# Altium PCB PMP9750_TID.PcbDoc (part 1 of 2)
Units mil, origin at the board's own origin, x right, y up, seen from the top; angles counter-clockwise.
Board outline 3800 x 2050 mil, 2 copper layers (Top Layer, Bottom Layer), stack 62 mil thick; 72 components, 37 nets, 177 pads, 17 vias.
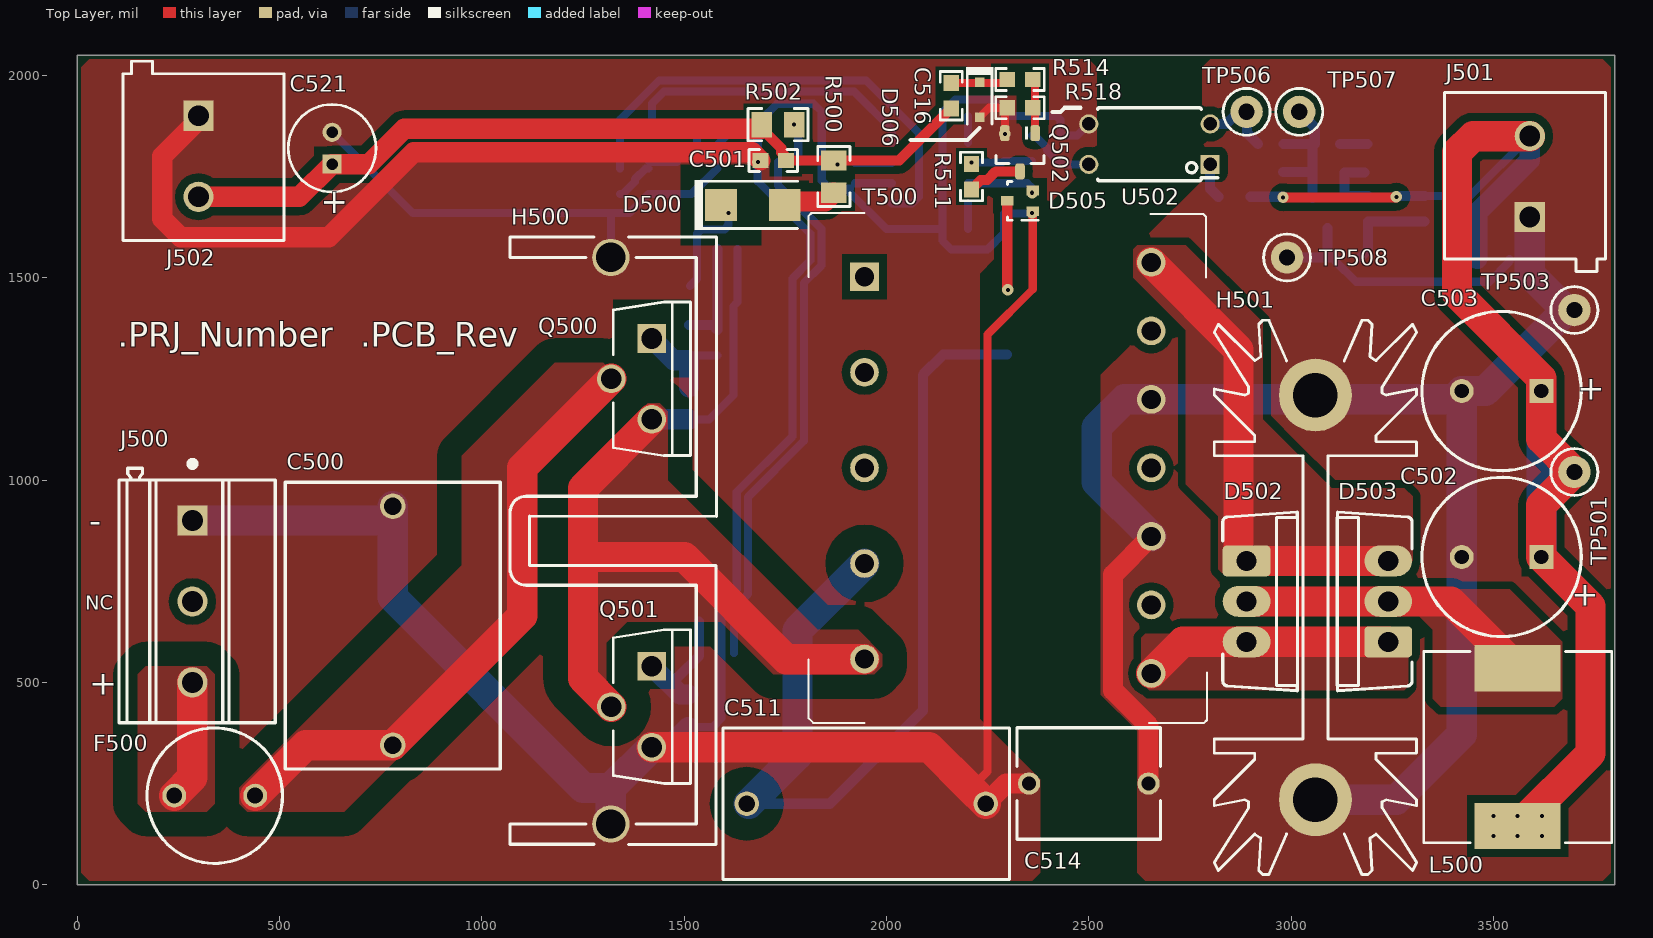
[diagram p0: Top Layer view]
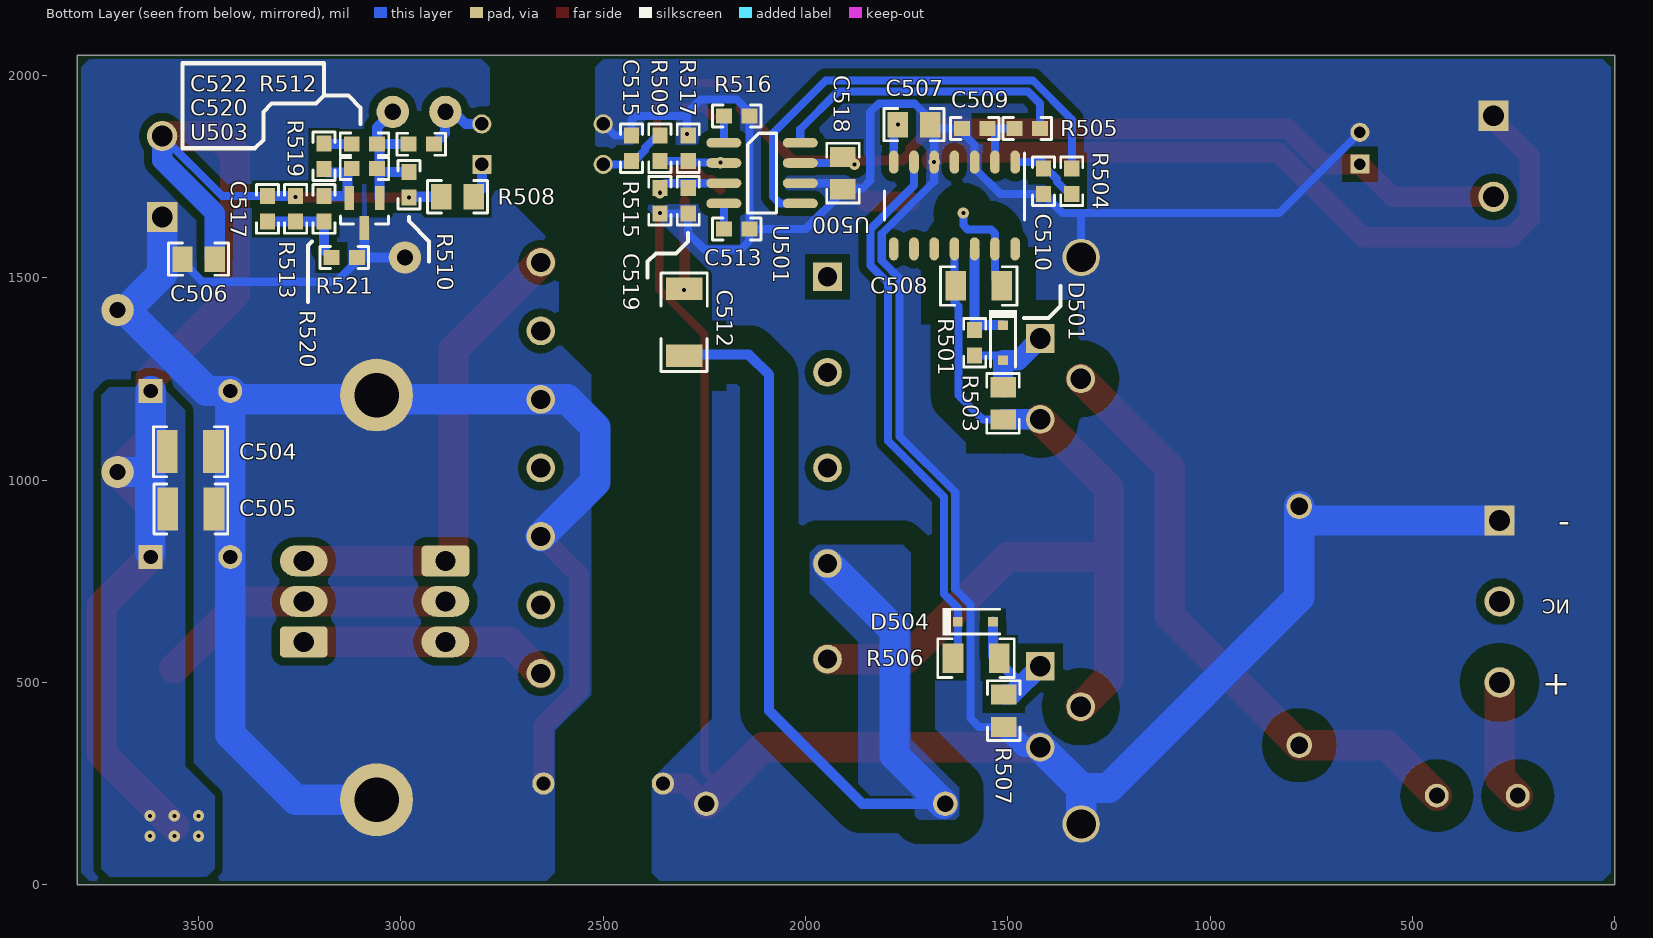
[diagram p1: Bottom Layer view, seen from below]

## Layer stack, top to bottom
Top Solder: solder mask 0.4, Solder Resist, Dk 3.5
Top Layer: signal copper 1.4
Dielectric1: core 59.2, FR-4, Dk 4.8
Bottom Layer: signal copper 1.4
Bottom Solder: solder mask 0.4, Solder Resist, Dk 3.5

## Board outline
0,0 3800,0 3800,2050 0,2050

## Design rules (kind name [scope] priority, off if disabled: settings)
AcuteAngle [All] p1: minimum=4.50000000000000E+0001 checktracksonly=FALSE
AssemblyTestPointUsage [All] p1: valid=2
Clearance Clearance_1 [InNetClass('HV_pri') vs InNet('GND')] p1: gap=60
Clearance Clearance_Keepouts [((IsTrack Or IsArc) And Not InPoly) And IsFree and IsKeepOut vs ((IsTrack Or IsArc) And Not InPoly) And IsFree and IsKeepOut] p2: gap=0
Clearance Clearance_BoardEdge_MountingHoles [OnCopper and InComponentClass('Mounting Holes') vs IsKeepOut] p3: gap=40
Clearance Clearance_BoardEdge_Poly [OnCopper and InPoly vs IsKeepOut] p4: gap=25
Clearance Clearance_BoardEdge [OnCopper and Not InComponentClass('Logo') and not InComponentClass('FiducialMark') and not InRegion(1000,500,4000,800) and Not IsKeepout vs IsKeepOut] p5: gap=75
Clearance Clearance_Poly [InPolygon] p6: gap=20
Clearance [All] p7: gap=7.87
ComponentClearance ComponentClearance_MountingHoles_FiducialMarks [InComponentClass('Mounting Holes') vs InComponentClass('FiducialMark')] p1: gap=20 collisioncheckmode=3 verticalgap=10 showdistances=FALSE
ComponentClearance ComponentClearance_Shunt [InComponentClass('Header') vs InComponentClass('Shunt')] p2: gap=0 collisioncheckmode=3 verticalgap=0 showdistances=FALSE
ComponentClearance ComponentClearance_Logo [InComponentClass('Logo')] p3: gap=5 collisioncheckmode=3 verticalgap=10 showdistances=FALSE
ComponentClearance ComponentClearance_ScrewToNut [(HasFootprint('NY PMS 440 0025 PH')) vs (HasFootprint('Keystone_1902C'))] p4: gap=20 collisioncheckmode=3 verticalgap=100000 showdistances=FALSE
ComponentClearance ComponentClearance_MountingHoles [InComponentClass('Mounting Holes')] p5: gap=20 collisioncheckmode=3 verticalgap=10 showdistances=FALSE
ComponentClearance ComponentClearance_SmallPassives [HasFootprint('0201*') or HasFootprint('0402*') or HasFootprint('0508') or HasFootprint('0603*') or HasFootprint('0612') or HasFootprint('0805*') or HasFootprint('0815*') or HasFootprint('0830*') or HasFootprint('1206*') or HasFootprint('1210*') or HasFootprint('1808*') or HasFootprint('1812*') or HasFootprint('1825*') or HasFootprint('2010*') or HasFootprint('2220*') or HasFootprint('2225*') or HasFootprint('2512*') or HasFootprint('2728*') or HasFootprint('3518*') vs HasFootprint('0201*') or HasFootprint('0402*') or HasFootprint('0508') or HasFootprint('0603*') or HasFootprint('0612') or HasFootprint('0805*') or HasFootprint('0815*') or HasFootprint('0830*') or HasFootprint('1206*') or HasFootprint('1210*') or HasFootprint('1808*') or HasFootprint('1812*') or HasFootprint('1825*') or HasFootprint('2010*') or HasFootprint('2220*') or HasFootprint('2225*') or HasFootprint('2512*') or HasFootprint('2728*') or HasFootprint('3518*')] p6: gap=20 collisioncheckmode=3 verticalgap=20 showdistances=FALSE
ComponentClearance ComponentClearance_THtoSMT [IsThruComponent vs IsSMTComponent] p7: gap=10 collisioncheckmode=3 verticalgap=10 showdistances=FALSE
ComponentClearance ComponentClearance_THtoTH [IsThruComponent vs IsThruComponent] p8: gap=10 collisioncheckmode=3 verticalgap=10 showdistances=FALSE
ComponentClearance [All] p9: gap=10 collisioncheckmode=3 verticalgap=10 showdistances=FALSE
DiffPairsRouting [All] p1: maxlimit=100 minlimit=10 mostfreqgap=10 toplayer_minwidth=15 toplayer_maxwidth=15 toplayer_prefwidth=15 bottomlayer_minwidth=15 bottomlayer_maxwidth=15 bottomlayer_prefwidth=15 maxuncoupledlength=1000
FabricationTestPointUsage TestPointUsage [All] p1: valid=2 allowmultiple=FALSE
FabricationTestpoint Testpoint [All] p1: side=3 testpointundercomponent=TRUE minsize=40 maxsize=100 preferedsize=60 minholesize=0 maxholesize=40 preferedholesize=32 testpointgrid=1 allowsidetop=TRUE allowsidebottom=TRUE usegrid=TRUE gridtolerance=0.01
FanoutControl Fanout_LCC [IsLCC] p1: bgadir=Out bgaviamode=Centered fanoutstyle=Auto fanoutdirection=Alternating viagrid=1 // Fanout_LCC (Default Rule)
FanoutControl Fanout_BGA [IsBGA] p2: bgadir=Out bgaviamode=Centered fanoutstyle=Auto fanoutdirection=Alternating viagrid=1 // Fanout_BGA (Default Rule)
FanoutControl Fanout_Default [All] p4: bgadir=Out bgaviamode=Centered fanoutstyle=Auto fanoutdirection=Alternating viagrid=1 // Fanout_Default (Default Rule)
FanoutControl Fanout_Small [(CompPinCount < 5)] p5: bgadir=Out bgaviamode=Centered fanoutstyle=Auto fanoutdirection=OutThenIn viagrid=1 // Fanout_Small (Default Rule)
Height [All] p1: minheight=0 maxheight=3000 prefheight=500
HoleSize [All] p1: absolutevalues=TRUE maxlimit=251 minlimit=7 maxpercent=80.000 minpercent=20.000
MinimumAnnularRing MinimumAnnularRing_ThermalPadVias [IsVia and InAnyComponent] p1: minimumring=5.91
MinimumAnnularRing [All] p2: minimumring=6
MinimumSolderMaskSliver MinimumSolderMaskSliver_Logo [InComponentClass('Logo') vs InComponentClass('Logo')] p1: minsoldermaskwidth=0.7
MinimumSolderMaskSliver [All] p2: minsoldermaskwidth=2
PlaneConnect [All] p1: planeconnectstyle=Relief reliefexpansion=10 reliefentries=4 reliefconductorwidth=10 reliefairgap=10
PolygonConnect PolygonConnect_8 [All vs IsNamedPolygon('C508_2') Or  IsNamedPolygon('B+') Or  IsNamedPolygon('Vout') Or  IsNamedPolygon('VSEC') Or  IsNamedPolygon('D502_3') Or  IsNamedPolygon('F500_2') Or  IsNamedPolygon('VCS') Or  IsNamedPolygon('D502_1')] p1: connectstyle=Direct reliefconductorwidth=10 reliefentries=4 polygonreliefangle="90 Angle" airgapwidth=10
PolygonConnect PolygonConnect_7 [All vs IsNamedPolygon('C508_2') Or  IsNamedPolygon('D502_1') Or  IsNamedPolygon('VCS') Or  IsNamedPolygon('D502_3') Or  IsNamedPolygon('B+')] p2: connectstyle=Direct reliefconductorwidth=10 reliefentries=4 polygonreliefangle="90 Angle" airgapwidth=10
PolygonConnect PolygonConnect_6 [All vs IsNamedPolygon('GND2') Or  IsNamedPolygon('SGND') Or  IsNamedPolygon('GND1') Or  IsNamedPolygon('C901_1') Or  IsNamedPolygon('SGND') Or  IsNamedPolygon('GND2') Or  IsNamedPolygon('GND1')] p3: connectstyle=Direct reliefconductorwidth=10 reliefentries=4 polygonreliefangle="90 Angle" airgapwidth=10
PolygonConnect PolygonConnect_5 [All vs IsNamedPolygon('GND1') Or  IsNamedPolygon('GND1')] p4: connectstyle=Direct reliefconductorwidth=10 reliefentries=4 polygonreliefangle="90 Angle" airgapwidth=10
PolygonConnect PolygonConnect_4 [All vs IsNamedPolygon('C21_1') Or  IsNamedPolygon('C5_1') Or  IsNamedPolygon('C12_2') Or  IsNamedPolygon('C2_2') Or  IsNamedPolygon('C13_1') Or  IsNamedPolygon('C28_1') Or  IsNamedPolygon('C6_1') Or  IsNamedPolygon('GND') Or  IsNamedPolygon('GND2') Or  IsNamedPolygon('C14_1') Or  IsNamedPolygon('C13_1') Or  IsNamedPolygon('Q1_3') Or  IsNamedPolygon('C14_1') Or  IsNamedPolygon('C5_1') Or  IsNamedPolygon('GND2') Or  IsNamedPolygon('C28_1') Or  IsNamedPolygon('D5_2') Or  IsNamedPolygon('D6_2') Or  IsNamedPolygon('D2_1') Or  IsNamedPolygon('C12_2') Or  IsNamedPolygon('D2_1') Or  IsNamedPolygon('C4_1') Or  IsNamedPolygon('C4_1') Or  IsNamedPolygon('C2_2') Or  IsNamedPolygon('GND') Or  IsNamedPolygon('C33_1') Or  IsNamedPolygon('C9_1')] p5: connectstyle=Direct reliefconductorwidth=10 reliefentries=4 polygonreliefangle="90 Angle" airgapwidth=10
PolygonConnect PolygonConnect_3 [All vs IsNamedPolygon('C28_1') Or  IsNamedPolygon('C12_2') Or  IsNamedPolygon('C28_1') Or  IsNamedPolygon('C9_1') Or  IsNamedPolygon('D5_2') Or  IsNamedPolygon('C12_2') Or  IsNamedPolygon('C2_2') Or  IsNamedPolygon('C14_1') Or  IsNamedPolygon('C4_1') Or  IsNamedPolygon('C14_1') Or  IsNamedPolygon('D6_2') Or  IsNamedPolygon('GND2') Or  IsNamedPolygon('Q1_3') Or  IsNamedPolygon('C5_1') Or  IsNamedPolygon('D2_1') Or  IsNamedPolygon('C4_1') Or  IsNamedPolygon('C13_1') Or  IsNamedPolygon('C5_1') Or  IsNamedPolygon('C13_1') Or  IsNamedPolygon('C33_1') Or  IsNamedPolygon('D2_1') Or  IsNamedPolygon('GND') Or  IsNamedPolygon('GND') Or  IsNamedPolygon('GND2') Or  IsNamedPolygon('C2_2') Or  IsNamedPolygon('C6_1') Or  IsNamedPolygon('C21_1')] p6: connectstyle=Direct reliefconductorwidth=10 reliefentries=4 polygonreliefangle="90 Angle" airgapwidth=10
PolygonConnect PolygonConnect_2 [All vs IsNamedPolygon('C21_1') Or  IsNamedPolygon('C4_1') Or  IsNamedPolygon('D5_2') Or  IsNamedPolygon('C5_1') Or  IsNamedPolygon('C14_1') Or  IsNamedPolygon('C13_1') Or  IsNamedPolygon('C4_1') Or  IsNamedPolygon('C33_1') Or  IsNamedPolygon('C12_2') Or  IsNamedPolygon('D2_1') Or  IsNamedPolygon('C2_2') Or  IsNamedPolygon('C28_1') Or  IsNamedPolygon('C12_2') Or  IsNamedPolygon('D2_1') Or  IsNamedPolygon('C5_1') Or  IsNamedPolygon('Q1_3') Or  IsNamedPolygon('GND') Or  IsNamedPolygon('D6_2') Or  IsNamedPolygon('C6_1') Or  IsNamedPolygon('C2_2') Or  IsNamedPolygon('C14_1') Or  IsNamedPolygon('C28_1') Or  IsNamedPolygon('C13_1') Or  IsNamedPolygon('C9_1') Or  IsNamedPolygon('GND')] p7: connectstyle=Direct reliefconductorwidth=10 reliefentries=4 polygonreliefangle="90 Angle" airgapwidth=10
PolygonConnect PolygonConnect_1 [All vs IsNamedPolygon('C28_1') Or  IsNamedPolygon('D5_2') Or  IsNamedPolygon('C5_1') Or  IsNamedPolygon('C5_1') Or  IsNamedPolygon('D2_1') Or  IsNamedPolygon('C21_1') Or  IsNamedPolygon('C9_1') Or  IsNamedPolygon('C4_1') Or  IsNamedPolygon('C14_1') Or  IsNamedPolygon('C28_1') Or  IsNamedPolygon('C6_1') Or  IsNamedPolygon('C12_2') Or  IsNamedPolygon('C33_1') Or  IsNamedPolygon('C4_1') Or  IsNamedPolygon('C13_1') Or  IsNamedPolygon('C12_2') Or  IsNamedPolygon('D6_2') Or  IsNamedPolygon('C2_2') Or  IsNamedPolygon('C14_1') Or  IsNamedPolygon('D2_1') Or  IsNamedPolygon('C2_2') Or  IsNamedPolygon('C13_1')] p8: connectstyle=Direct reliefconductorwidth=10 reliefentries=4 polygonreliefangle="90 Angle" airgapwidth=10
PolygonConnect [All] p9: connectstyle=Relief reliefconductorwidth=10 reliefentries=4 polygonreliefangle="90 Angle" airgapwidth=10
RoutingVias ThermalPadVias [IsVia and InAnyComponent] p1: holewidth=7.87 width=19.68 viastyle="Through Hole" minholewidth=7.87 minwidth=19.68 maxholewidth=12.99 maxwidth=23.62
RoutingVias [All] p2: holewidth=16 width=34 viastyle="Through Hole" minholewidth=7.87 minwidth=26 maxholewidth=40 maxwidth=65
SilkToBoardRegionClearance [Not ((IsComment or IsDesignator) And (Hide <> 'False')) and not InRegion(1000,500,4000,800)] p1:
SilkToSilkClearance SilkToSilkClearance_Pb-FreeLogo [(HasFootprint('Pb-Free_Overlay_Medium') OR HasFootprint('Pb-Free_Overlay_Small')) vs (HasFootprint('Pb-Free_Overlay_Medium') OR HasFootprint('Pb-Free_Overlay_Small'))] p1: silktosilkclearance=0
SilkToSilkClearance [All] p2: silktosilkclearance=1
SilkToSolderMaskClearance "Silk to Solder Mask Opening" [All] p1: minsilkscreentomaskgap=1 clearancetoexposedcopper=FALSE
SolderMaskExpansion [All] p1: expansion=1.97
UnpouredPolygon [All] p1: allowunpoured=FALSE
Width [All] p1: maxlimit=100 minlimit=6 preferedwidth=10 checkconnectedcopper=TRUE
13 further rules are at their usual default settings.

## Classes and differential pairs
net class HV_pri: B+ NetC508_1 NetC508_2 NetD501_2 NetF500_2 VCS
net class Sec: GND2 NetC517_2 NetC520_1 NetC520_2 NetC522_1 NetD502_1 NetD502_3 NetR508_1 NetR512_1 VOUT VSEC
net class LV_pri: BIAS GND NetC507_2 NetC509_1 NetC510_1 NetC512_2 NetC513_1 NetC515_1 NetC516_2 NetC519_1 NetD500_2 NetD504_1 NetD504_2 NetQ502_1 NetQ502_3 NetR504_1 NetR505_1 NetR509_1 NetR516_2

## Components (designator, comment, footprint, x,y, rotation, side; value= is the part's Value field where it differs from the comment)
C500 "450MPK225J" MPK_1800x2000x1350 780,640 r90 top
C501 "UMK107AB7105KA-T" 0603 1720,1790 r0 top
C502 "35ZLH1000MEFC12.5X20" CAPPR5-10X20 3520,810 r180 top
C503 "35ZLH1000MEFC12.5X20" CAPPR5-10X20 3520,1220 r180 top
C504 "C3225X7R1H335M" 1210 3520,1070 r180 bottom
C505 "C3225X7R1H335M" 1210 3519,928.5 r180 bottom
C506 "08055C104KAT2A" 0805_HV 3500,1546 r0 bottom
C507 "GMK212B7105KG-T" 0805_HV 1732,1878.5 r0 bottom
C508 "12065C104KAT2A" 1206 1572,1479.6 r0 bottom
C509 "C0603C220J5GACTU" 0603 1582,1868.5 r0 bottom
C510 "C0603C220J5GACTU" 0603 1412,1738.5 r270 bottom
C511 "121MPE333J" CAPRR1500W80L1800T950H1800 1950,200 r0 top
C512 "VJ1808Y101KXEAT5Z" 1808 2300,1390 r90 bottom
C513 "C0603C474K4RACTU" 0603 2170,1620 r180 bottom
C514 "DE6E3KJ222MN3A" E_900x700x900 2500,250 r180 top
C515 "C0603C103K5RACTU" 0603 2430,1820 r90 bottom
C516 "06033C104JAT2A" 0603 2160,1950 r90 top
C517 "C0603C222K5RAC" 0603 3330,1670 r270 bottom
C518 "08053C224JAT2A" 0805_HV 1907.43,1758.5 r270 bottom
C519 "C0603C105K4PACTU" 0603 2290,1690 r270 bottom
C520 "C1608C0G1H101J" 0603 3090,1770 r180 bottom
C521 "25ML22MEFC5X5" ML_500x500 630,1820 r90 top
C522 "06031C332KAT2A" 0603 3090,1830 r180 bottom
D500 "BYG20J-E3/TR" SMA 1670,1680 r0 top
D501 "BAT54HT1G" sod-323 1512,1339.61 r270 bottom
D502 "VF40100C-E3/4W" TO-220AB 2890,700 r270 top
D503 "VF40100C-E3/4W" TO-220AB 3240,700 r90 top
D504 "BAT54HT1G" sod-323 1580,650 r180 bottom
D505 "BAV99WT1G" SOT-323 2330,1690 r180 top
D506 "MMDL914-TP" sod-323 2230,1940 r270 top
F500 "37212000001" FUSE_372 340,220 r180 top
H500 "578622B03200G" HSINK_578622B03200G 1320,850 r270 top
H501 "513002B02500G" HSINK_513201B02500 3060,710 r90 top
J500 "1715734" Phoenix_1715734 284.83,700 r270 top
J501 "1715721" PhoenixContact_1715721 3590,1750 r90 top
J502 "1715721" PhoenixContact_1715721 300,1800 r270 top
L500 "7443320100" WE-HCC_1210 3560,340 r270 top
Q500 "STP14NM50N" TO-220AB_100mil 1420,1350 r270 top
Q501 "STP14NM50N" TO-220AB_100mil 1420,540 r270 top
Q502 "FMMT620TA" SOT-23 2330,1810 r270 top
R500 "CRCW08052R20JNEA" 0805_HV 1870,1750 r270 top
R501 "CRCW06033R00JNEA" 0603 1582,1339.61 r270 bottom
R502 "ERJ-6RQF1R0V" 0805_HV 1732,1878.5 r180 top
R503 "CRCW080520K0FKEA" 0805_HV 1512,1189.6 r270 bottom
R504 "CRCW060351R1FKEA" 0603 1342,1738.5 r270 bottom
R505 "CRCW060351R1FKEA" 0603 1452,1868.5 r0 bottom
R506 "CRCW12063R30JNEA" 1206 1578.66,560 r180 bottom
R507 "CRCW080520K0FKEA" 0805_HV 1510,430 r270 bottom
R508 "CRCW08054K99FKEA" 0805_HV 2860,1700 r0 bottom
R509 "CRCW0603511RFKEA" 0603 2360,1820 r90 bottom
R510 "CRCW060310K0FKEA" 0603 2980,1730 r270 bottom
R511 "CRCW0603100RFKEA" 0603 2210,1750 r90 top
R512 "CRCW060315R0JNEA" 0603 2950,1830 r0 bottom
R513 "CRCW060325K5FKEA" 0603 3260,1670 r90 bottom
R514 "CRCW060349K9FKEA" 0603 2330,1990 r0 top
R515 "CRCW0603200RFKEA" 0603 2360,1690 r90 bottom
R516 "CRCW060320K0FKEA" 0603 2170,1900 r0 bottom
R517 "CRCW06033K40FKEA" 0603 2290,1820 r270 bottom
R518 "CRCW0603100KFKEA" 0603 2330,1920 r180 top
R519 "CRCW060310K0FKEA" 0603 3190,1800 r270 bottom
R520 "CRCW06031K00FKEA" 0603 3190,1670 r270 bottom
R521 "CRCW06032K49FKEA" 0603 3140,1550 r0 bottom
T500 "G135043LF" XFMR_GCI-1240x965x1213 2300,1030 r0 top
TP501 "5000" Keystone5000 3700,1020 r0 top
TP503 "5001" Keystone5001 3700,1420 r90 top
TP506 "5003" Keystone5003 2890,1910 r90 top
TP507 "5002" Keystone5002 3020,1910 r90 top
TP508 "5001" Keystone5001 2990,1550 r90 top
U500 "UCC27714D" D0014A_N 1632,1678.5 r270 bottom
U501 "UCC25600D" D0008A_N 2107.43,1758.5 r180 bottom
U502 "PC817X4NSZ0F" DIP762W60P254L460H350Q4B 2650,1830 r180 top
U503 "TL431ACDBZR" DBZ0003A_N 3090,1660 r270 bottom

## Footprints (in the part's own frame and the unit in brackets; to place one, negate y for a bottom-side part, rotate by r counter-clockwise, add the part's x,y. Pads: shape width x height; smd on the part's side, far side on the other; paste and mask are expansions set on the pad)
0603 [mm] "0603 from SM-752 data"
  rect 1x0.95 smd: 1(-0.8,0) 2(0.8,0)
  silkscreen extent -1.52,-0.69 1.52,0.69, body extent -0.87,-0.47 0.87,0.47, height 0.85
0805_HV [mil] "0805 with 30mil clearance between pads"
  rect 50x63 smd: 1(-40,0) 2(40,0)
  silkscreen extent -74,-40 74,40, body extent -43,-29 43,29, height 43
1206 [mm] "1206 from SM-752 data"
  rect 1.3x1.85 smd: 1(-1.45,0) 2(1.45,0)
  silkscreen extent -2.4,-1.21 2.4,1.21, body extent -1.7,-0.9 1.7,0.9, height 1.35
1210 [mm] "1210 from SM-752 data"
  rect 1.3x2.7 smd: 1(-1.45,0) 2(1.45,0)
  silkscreen extent -2.32,-1.57 2.32,1.57, body extent -1.7,-1.35 1.7,1.35, height 1.35
1808 [mm] "Chip Capacitor, Body 4.6x2.0mm, IPC Medium Density"
  rect 1.4x2.3 smd: 1(-2.1,0) 2(2.1,0)
  silkscreen extent -3.1,-1.45 3.1,1.45, body extent -2.47,-1.2 2.47,1.2, height 2.03
CAPPR5-10X20 [mm] "Capacitor, Electrolytic, Radial; Body 10 x 20 mm (Dia.xH typ); Pin Spacing 5 mm (typ)"
  rect 1.5x1.5 hole 0.9: 1(-2.5,0)
  round 1.5 hole 0.9: 2(2.5,0)
  silkscreen extent -5,-5 5,5, body extent -5.01,-5.01 5.01,5.01, height 22
CAPRR1500W80L1800T950H1800 [mm] "RUBYCON"
  round 1.55 hole 1.05: 1(-7.5,0) 2(7.5,0)
  silkscreen extent -9,-4.75 9,4.75, body extent -9,-4.75 9,4.75, height 19
D0008A_N [mm] "SOIC, 8-Leads, Body 4.9x3.9mm, Pitch 1.27mm, IPC Medium Density"
  oval 2.2x0.6 smd: 1(-2.4,1.905) 2(-2.4,0.635) 3(-2.4,-0.635) 4(-2.4,-1.905) 5(2.4,-1.905) 6(2.4,-0.635) 7(2.4,0.635) 8(2.4,1.905)
  silkscreen extent -0.9,-2.5 0.9,2.5, body extent -3,-2.45 3,2.45, height 1.63
D0014A_N [mm] "SOIC, 14-Leads, Body 8.7x3.9mm, Pitch 1.27mm, IPC Medium Density"
  oval 1.45x0.6 smd: 1(-2.725,3.81) 2(-2.725,2.54) 3(-2.725,1.27) 4(-2.725,0) 5(-2.725,-1.27) 6(-2.725,-2.54) 7(-2.725,-3.81) 8(2.725,-3.81) 9(2.725,-2.54) 10(2.725,-1.27) 11(2.725,0) 12(2.725,1.27) 13(2.725,2.54) 14(2.725,3.81)
  silkscreen extent -3.3,-4.4 0.9,4.4, body extent -3.02,-4.32 3.02,4.32, height 1.6
DBZ0003A_N [mm] "SOT23, 3-Leads, Body 2.9x1.3mm, Pitch 0.95mm, Lead Span 2.4mm, IPC Medium Density"
  rect 1.5x0.6 smd: 1(-0.95,0.95) 2(-0.95,-0.95) 3(0.95,0)
  silkscreen extent 0.2,-1.5 0.7,1.5, body extent -1.26,-1.46 1.26,1.46, height 0.96
DIP762W60P254L460H350Q4B [mm] "LITE-ON"
  rrect8% 1.2x1.2 hole 0.85: 1(-3.81,1.27)
  round 1.2 hole 0.85: 2(-3.81,-1.27) 3(3.81,-1.27) 4(3.81,1.27)
  silkscreen extent -4.29,-2.29 3.25,2.3, body extent -3.94,-2.29 3.94,2.3, height 4.3
E_900x700x900 [mm] "TH, 2- Leads, Body 9x7mm, Pin Spacing 7.5mm"
  round 1.4 hole 0.9: 1(-3.75,0) 2(3.75,0)
  silkscreen extent -4.5,-3.5 4.5,3.5, body extent -4.49,-3.5 4.49,3.5, height 11.96
FUSE_372 [mm] "LITTELFUSE"
  round 1.5 hole 1: 1(-2.54,0) 2(2.54,0)
  silkscreen extent -4.25,-4.25 4.25,4.25, body extent -4.26,-4.26 4.26,4.26, height 8
HSINK_513201B02500 [mil] "Aavid"
  round 180 hole 110.24: 1(-500,0) 2(500,0)
  silkscreen extent -685,-250 685,250, body extent -685,-250 685,250, height 2000
HSINK_578622B03200G [mm] "Twin Channel Style Heat Sink, TO-220"
  round 2.35 hole 1.85: 1(-17.78,-0.025) 2(17.78,-0.025)
  silkscreen extent -19.06,-6.35 19.07,6.6, body extent -19.06,-6.36 19.03,6.69, height 25.4
Keystone5000 [mil] "For Keystone 500x miniature loop terminals"
  round 80 hole 40: 1(0,0)
  silkscreen extent -58,-58 58,58, body extent -49,-49 49,49, height 182
Keystone5001 [mil] "For Keystone 500x miniature loop terminals"
  round 80 hole 40: 1(0,0)
  silkscreen extent -58,-58 58,58, body extent -49,-49 49,49, height 182
Keystone5002 [mil] "For Keystone 500x miniature loop terminals"
  round 80 hole 40: 1(0,0)
  silkscreen extent -58,-58 58,58, body extent -49,-49 49,49, height 182
Keystone5003 [mil] "For Keystone 500x miniature loop terminals"
  round 80 hole 40: 1(0,0)
  silkscreen extent -58,-58 58,58, body extent -49,-49 49,49, height 182
ML_500x500 [mm] "Rubycon"
  rect 1.2x1.2 hole 0.711: 1(-1,0)
  round 1.2 hole 0.711: 2(1,0)
  silkscreen extent -2.75,-2.75 2.75,2.75, body extent -2.73,-2.75 2.75,2.75, height 6.51
MPK_1800x2000x1350 [mm] "Rubycon"
  round 1.6 hole 1.1: 1(-7.5,0) 2(7.5,0)
  silkscreen extent -9,-6.75 9,6.75, body extent -9,-6.75 9,6.75, height 20
Phoenix_1715734 [mm] "Phoenix"
  rect 1.9x1.9 hole 1.321: 1(-5.08,0)
  round 1.9 hole 1.321: 2(0,0) 3(5.08,0)
  silkscreen extent -8.76,-4.6 7.62,5.2, body extent -8.36,-4.6 7.62,5.2, height 14.2
PhoenixContact_1715721 [mm] "Phoenix Contact 1715721 used on LM3445 design from Longmont"
  rect 1.905x1.905 hole 1.3: 1(-2.54,0)
  round 1.9 hole 1.3: 2(2.54,0)
  silkscreen extent -5.97,-4.75 5.28,5.36, body extent -5.82,-4.6 5.08,5.2, height 14.2
SMA [mm] "Molded Diode, 2-Leads, Body 4.3x2.6mm, IPC Medium Density, based on OnSemi component dimensions and land pattern"
  rect 2x2 smd: 1(-2,0) 2(2,0)
  silkscreen extent -3.66,-1.57 2.79,1.57, body extent -2.6,-1.3 2.6,1.3, height 2.42
sod-323 [mm] "NXP recommended land pattern"
  rect 0.6x0.6 smd paste-0.05: 1(-1.1,0) 2(1.1,0)
  silkscreen extent -2.06,-0.86 1.53,0.86, body extent -1.3,-0.67 1.3,0.68, height 1.1
SOT-23 [mm] "SOT23, 3-Leads, Body 2.9x1.3mm, Pitch 0.95mm, Lead Span 2.5mm, IPC Medium Density"
  rrect50% 1x0.6 smd: 1(-1.2,0.95) 2(-1.2,-0.95) 3(1.2,0)
  silkscreen extent -1.63,-1.5 0.7,1.5, body extent -1.16,-1.45 1.21,1.45, height 1
SOT-323 [mm] "Zetex recommended land pattern.  March 2007"
  rect 0.8x0.6 smd: 1(-0.8,0.65) 2(-0.8,-0.65) 3(0.8,0)
  silkscreen extent -1.14,-1.22 0.77,1.22, body extent -1.13,-1.13 1.12,1.12, height 1.13
TO-220AB [mil] "Copied from Altium's version of TO3B"
  rrect25% 76x118.11 hole 50: 1(-100,0)
  oval 76x118.11 hole 50: 2(0,0) 3(100,0)
  silkscreen extent -221,-59 221,126, body extent -221,-59 221,126, height 765
TO-220AB_100mil [mm] "High Voltage staggered pins"
  rect 1.8x1.8 hole 1.3: 1(0,0)
  round 1.8 hole 1.3: 2(2.54,-2.54) 3(5.08,0)
  silkscreen extent -2.29,-2.41 7.36,2.43, body extent -2.28,-2.84 7.37,2.43, height 22.88
WE-HCC_1210 [mm] "WURTH"
  rect 2.9x5.4 smd: 1(-4.95,0) 2(4.95,0)
  silkscreen extent -6,-5.9 6,5.9, body extent -6,-5.85 6,5.85, height 10
XFMR_GCI-1240x965x1213 [mm] "XFMR-GCI"
  rect 1.8x1.8 hole 1.2: 1(-9,12)
  round 1.8 hole 1.2: 2(-9,6) 3(-9,0) 4(-9,-6) 5(-9,-12) 6(9,-12.9) 7(9,-8.6) 8(9,-4.3) 9(9,0) 10(9,4.3) 11(9,8.6) 12(9,12.9)
  silkscreen extent -12.52,-16.02 12.5,16, body extent -12.4,-15.8 12.3,15.9, height 30.81

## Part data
C500: "CAP, Film, 2.2 µF, 450 V, +/- 5%, TH"
C501: "CAP, CERM, 1 µF, 50 V, +/- 10%, X7R, 0603"
C502 C503: library part EEU-FR1V681, "CAP, AL, 680uF, 35V, +/-20%, TH"
C504 C505: "CAP, CERM, 3.3uF, 50V, +/-20%, X7R, 1210"
C506: "CAP, CERM, 0.1uF, 50V, +/-10%, X7R, 0805"
C507: "CAP, CERM, 1uF, 35V, +/-10%, X7R, 0805"
C508: "CAP, CERM, 0.1 µF, 50 V, +/- 10%, X7R, 1206"
C509 C510: "CAP, CERM, 22 pF, 50 V, +/- 5%, C0G/NP0, 0603"
C511: "CAP, Film, 0.033uF, 1250V, +/-5%, TH"
C512: "CAP, CERM, 100pF, 500V, +/-10%, X7R, 1808"
C513: "CAP, CERM, 0.47uF, 16V, +/-10%, X7R, 0603"
C514: "CAP, CERM, 2200 pF, 300 V, +/- 20%, E, TH, 2- Leads, Body 9x7mm, Pin Spacing 7.5mm"
C515: "CAP, CERM, 0.01uF, 50V, +/-10%, X7R, 0603"
C516: "CAP, CERM, 0.1 µF, 25 V, +/- 5%, X7R, 0603"
C517: "CAP, CERM, 2200pF, 50V, +/-10%, X7R, 0603"
C518: "CAP, CERM, 0.22uF, 25V, +/-5%, X7R, 0805"
C519: "CAP, CERM, 1uF, 16V, +/-10%, X5R, 0603"
C520: "CAP, CERM, 100pF, 50V, +/-5%, C0G/NP0, 0603"
C521: "CAP, AL, 22 µF, 25 V, +/- 20%, TH"
C522: "CAP, CERM, 3300pF, 100V, +/-10%, X7R, 0603"
D500: "Diode, Ultrafast, 600V, 1.5A, SMA"
D501 D504: "Diode, Schottky, 30V, 0.2A, SOD-323"
D502 D503: "Diode, Schottky, 100 V, 20 A, TH"
D505: "Diode, P-N, 70V, 0.2A, SOT-323"
D506: "Diode, Switching, 100 V, 0.2 A, SOD-323"
F500: "Fuse, 2 A, 250 V, TH"
H500: "Twin Channel Style Heat Sink, TO-220, Vertical"
H501: library part 513201B02500G, "BOARD LEVEL HEATSINK .5\" TO-220"
J500: "TERM BLOCK 3POS 5.08MM, TH"
J501 J502: "Conn Term Block, 2POS, 5.08mm, TH"
L500: "Inductor, Shielded Drum Core, Ferrite, 1 µH, 24 A, 0.0012 ohm, SMD"
Q500 Q501: library part SPP06N80C3, "MOSFET N-CH 500V 12A TO-220"
Q502: library part "MMBT2222A, Fairchild Semiconductor", "TRANS NPN 80V 1.5A SOT23-3"
R500: "RES, 2.2, 5%, 0.125 W, 0805"
R501: "RES, 3.0 ohm, 5%, 0.1W, 0603"
R502: "RES, 1.00 ohm, 1%, 0.125W, 0805"
R503 R507: "RES, 20.0k ohm, 1%, 0.125W, 0805"
R504 R505: "RES, 51.1, 1%, 0.1 W, 0603"
R506: "RES, 3.3, 5%, 0.25 W, 1206"
R508: "RES, 4.99k ohm, 1%, 0.125W, 0805"
R509: "RES, 511, 1%, 0.1 W, 0603"
R510 R519: "RES, 10.0k ohm, 1%, 0.1W, 0603"
R511: "RES, 100, 1%, 0.1 W, 0603"
R512: "RES, 15 ohm, 5%, 0.1W, 0603"
R513: "RES, 25.5k ohm, 1%, 0.1W, 0603"
R514: "RES, 49.9 k, 1%, 0.1 W, 0603"
R515: "RES, 200 ohm, 1%, 0.1W, 0603"
R516: "RES, 20.0k ohm, 1%, 0.1W, 0603"
R517: "RES, 3.40k ohm, 1%, 0.1W, 0603"
R518: "RES, 100 k, 1%, 0.1 W, 0603"
R520: "RES, 1.00k ohm, 1%, 0.1W, 0603"
R521: "RES, 2.49k ohm, 1%, 0.1W, 0603"
T500: "Transformer, 360uH, TH"
TP501: "Test Point, Miniature, Red, TH"
TP503 TP508: "Test Point, Miniature, Black, TH"
TP506: "Test Point, Miniature, Orange, TH"
TP507: "Test Point, Miniature, White, TH"
U500: "High-Speed,4A, 600V High-side Low-side Gate Driver Device, D0014A"
U501: "High-Performance Resonant Mode Controller with Voltage Control, 50 % Duty Cycle, -40 to +125 degC, 8-pin SOIC (D), Green (RoHS & no Sb/Br)"
U502: library part LTV-817, "Opto-Isolator, 1 Channel, TH"
U503: "Adjustable Precision Shunt Regulator, 34 ppm / degC, 100 mA, 0 to 70 degC, 3-pin SOT-23 (DBZ), Green (RoHS & no Sb/Br)"

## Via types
v1: diameter 28, hole 10, Top Layer to Bottom Layer, 17 vias

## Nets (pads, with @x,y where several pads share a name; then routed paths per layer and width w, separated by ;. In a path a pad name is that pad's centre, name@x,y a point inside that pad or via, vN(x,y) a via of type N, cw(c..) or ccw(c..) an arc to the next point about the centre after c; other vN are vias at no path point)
B+: C500.1 F500.1 Q500.2 | length 1520.6
  Top Layer w75: F500.1@440,220 564.72,344.72 C500.1@780,344.72 1100,664.72 1100,1030 Q500.2@1320,1250
BIAS: C501.2 C516.1 C518.1 C521.1 J502.2 R500.1 R502.2 U501.7 | length 2101.5
  Top Layer w25: R502.2@1692,1868 1740,1820 1740,1810 1760,1790 R500.1@1870,1790 2031.5,1790 C516.1@2160,1918.5
  Top Layer w50: J502.2@310,1700 549.37,1700 C521.1@630,1780.63 720.63,1780.63 808,1868 R502.2@1692,1868
  Bottom Layer w20: C518.1@1922.43,1783.5 U501.7@2012.94,1783.5
  other v1: 1878.89,1780
GND: C500.2 C501.1 C507.1 C509.2 C510.2 C511.2 C513.2 C514.2 C515.2 C518.2 C519.2 C521.2 D505.1 D506.2 H500.1 H500.2 J500.1 J502.1 Q501.3 Q502.2 R507.2 R515.1 R516.1 R517.1 R518.2 U500.3 U500.5 U501.6 U502.3 | length 11243.5
  Top Layer w20: 2207.64,237.64 2250,280 2250,1360 2361.5,1471.5 D505.1@2361.5,1664.41 ; D506.2@2230,1896.69 2253.31,1920 R518.2@2298.5,1920 ; Q502.2@2292.6,1857.24 R518.2@2292.6,1914.09
  Top Layer w50: J502.1@310,1900 210,1800 210,1646 256,1600 621.85,1600 831.85,1810 1668.5,1810 C501.1@1688.5,1790 ; C511.2@2245.28,200 2295.28,250 C514.2@2352.36,250
  Top Layer w75: Q501.3@1420,340 2105.28,340 2207.64,237.64 C511.2@2245.28,200
  Bottom Layer w20: C521.2@630,1859.37 829.37,1660 1365,1660 C510.2@1412,1707 1518.5,1707 1582,1770.5 U500.3@1582,1785.78 1582,1828.5 C509.2@1613.5,1860 ; H500.1@1319.02,1550 1319.02,1659.02 ; R507.2@1510,390 1571,390 1592.28,411.28 1592.28,692.28 1630,730 1630,970 1767.87,1107.87 1767.87,1498.38 1811.68,1542.19 1811.68,1608.82 1682,1738.5 v1(1682,1785.78) 1682,1868.5 C509.2@1613.5,1868.5 ; C507.1@1692,1878.5 1692,1892 1730,1930 1820,1930 1840,1910 1840,1740 1860,1720 C518.2@1910,1720 ; C518.2@1907.43,1712.57 2000,1620 C513.2@2138.5,1620 ; C518.2@1922.43,1733.5 U501.6@2012.94,1733.5 ; v1(2292.61,1855.67) 2292.61,1907.39 ; R515.1@2360,1658.5 C519.2@2290,1658.5 2290,1610 2250,1570 2160,1570 2138.5,1591.5 C513.2@2138.5,1620 ; U502.3@2500,1880 2471.5,1851.5 C515.2@2430,1851.5 2430,1890 2420,1900 2300,1900 2292.61,1907.39 ; C513.2@2138.5,1620 R516.1@2138.5,1900 2138.5,1908.5 2170,1940 2260,1940 2292.61,1907.39
  Bottom Layer w50: Q501.3@1420,340 1460,340 R507.2@1510,390
  Bottom Layer w75: J500.1@284.83,900 744.72,900 ; C500.2@780,935.28 780,710 1250.98,239.02 1319.02,239.02 ; H500.2@1319.02,150 1319.02,239.02 ; Q501.3@1420,340 1319.02,239.02
  other v1: 2360,1660
GND2: C502.2 C503.2 C504.2 C505.2 C506.2 C514.1 H501.1 H501.2 J501.1 R521.1 T500.8 T500.10 TP503.1 TP508.1 U503.3 | length 4484.4
  Top Layer w50: C514.1@2647.64,250 2647.64,392.36 2560,480 2560,766.38 T500.8@2654.33,860.71
  Bottom Layer w20: R521.1@3108.5,1541.5 3160,1490 3490,1490 3540,1540 C506.2@3540,1546
  Bottom Layer w25: TP508.1@2990,1550 R521.1@3108.5,1550 3090,1568.5 U503.3@3090,1622.6
  Bottom Layer w75: T500.8@2654.33,860.71 2520,995.04 2520,1130 2589.29,1199.29 T500.10@2654.33,1199.29 C503.2@3400.87,1199.29 ; H501.1@3060,210 3260,210 3421.57,371.57 C502.2@3421.57,810 C503.2@3421.57,1220 3480,1220 3680,1420 3590,1510 J501.1@3590,1650
NetC507_2: C507.2 R502.1 U500.7 | length 82.7
  Bottom Layer w20: U500.7@1782,1785.78 C507.2@1782,1868.5
  other v1: 1772,1878.5
NetC508_1: C508.1 D500.1 U500.13 | length 253.6
  Bottom Layer w20: C508.1@1514.91,1479.6 1532,1496.69 U500.13@1532,1571.22 1532,1609.68 1541.92,1619.6 1599.6,1619.6 1610,1630 v1(1610,1660)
